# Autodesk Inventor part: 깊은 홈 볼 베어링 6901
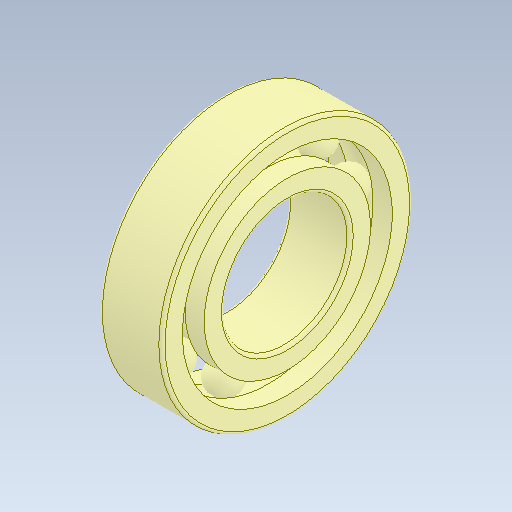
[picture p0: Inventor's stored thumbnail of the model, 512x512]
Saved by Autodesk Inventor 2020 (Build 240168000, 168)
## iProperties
Created: 2024-07
Part Number: 깊은 홈 볼 베어링 6901
Material: 강철, 연강
Description: 깊은 그루브 볼 베어링
Document SubType Name: Modeling
Designer: oem
Density: 7.85 g/cm^3
Appearance: 기본값
Author: jhkim
Sending System: Autodesk Inventor 2025
Preprocessor: ST-DEVELOPER v20
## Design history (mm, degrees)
feature "Solid1"
feature "Solid1:1"
feature "Solid1:2"
feature "Solid1:3"
feature "Solid1:4"
feature "Solid1:5"
feature "Solid1:6"
feature "Solid1:7"
feature "Solid1:8"
feature "Solid1:9"
feature "Solid1:10"
node "솔리드1"
node "솔리드2"
node "솔리드3"
node "솔리드4"
node "솔리드5"
node "솔리드6"
node "솔리드7"
node "솔리드8"
node "솔리드9"
node "솔리드10"
node "솔리드11"
